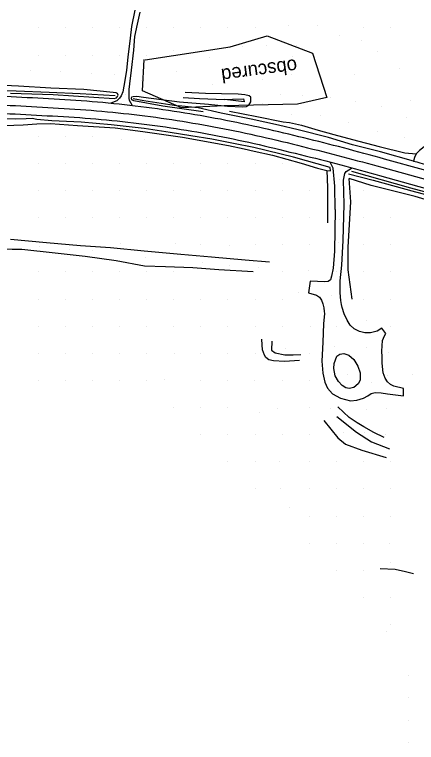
# Model space of a CAD drawing. Extents: x 524772 to 528246, y 273285 to 283088.
# Drawn here: x 526618.3 to 526762.8, y 276736 to 276997.8 of the extents above; entities that cross this region are included whole.
import ezdxf

# ---------------------------------------------------------------- set-up
doc = ezdxf.new("R2010")
doc.units = 0
for name, color, linetype in [('Exist DTM Crownline', 7, 'Continuous'), ('Exist Roads EOP', 7, 'Continuous'), ('Old_Level_12', 7, 'Continuous'), ('PH Exist DTM Breakline', 7, 'Continuous'), ('PH Exist DTM Point', 7, 'Continuous')]:
    doc.layers.add(name, color=color, linetype=linetype)

msp = doc.modelspace()

# ---------------------------------------------------------------- linework, layer by layer
at = {"layer": 'Exist DTM Crownline'}
msp.add_lwpolyline([(526750.37, 276942.86), (526764.67, 276938.9), (526778.8, 276934.96), (526793.27, 276930.79), (526807.53, 276926.68), (526821.79, 276922.52), (526835.38, 276918.67)], dxfattribs=at)
msp.add_spline([(526583.97, 276966.24), (526599.66, 276965.74), (526614.74, 276965.2), (526630.2, 276964.39), (526645.85, 276963.33), (526661.32, 276961.81), (526676.76, 276959.7), (526691.88, 276957.05), (526706.98, 276953.91), (526721.87, 276950.32), (526736.38, 276946.62), (526750.37, 276942.86)], degree=3, dxfattribs=at)
at = {"layer": 'Exist Roads EOP'}
for points in [[(526836.42, 276921.52), (526822.33, 276925.55), (526808.37, 276929.65), (526793.93, 276933.83), (526779.84, 276937.9), (526765.3, 276941.89), (526751.28, 276945.8)], [(526749.57, 276939.93), (526763.73, 276935.98), (526778.11, 276931.99), (526792.34, 276927.88), (526806.77, 276923.72), (526820.77, 276919.62), (526834.6, 276915.64)]]:
    msp.add_lwpolyline(points, dxfattribs=at)
for points in [[(526751.28, 276945.8), (526736.57, 276949.8), (526722.35, 276953.39), (526707.97, 276956.82), (526692.31, 276960.1), (526677.62, 276962.64), (526661.69, 276964.87), (526646.17, 276966.42), (526630.53, 276967.44), (526615.07, 276968.27), (526599.68, 276968.88), (526584.17, 276969.32)], [(526584.09, 276963.24), (526599.5, 276962.76), (526614.64, 276962.19), (526630, 276961.4), (526645.59, 276960.41), (526661, 276958.88), (526676.37, 276956.79), (526691.31, 276954.16), (526706.26, 276950.99), (526720.99, 276947.43), (526735.68, 276943.74), (526749.57, 276939.93)]]:
    msp.add_spline(points, degree=3, dxfattribs=at)
at = {"layer": 'Old_Level_12'}
msp.add_lwpolyline([(526665.21, 276981.52), (526695.79, 276986.19), (526709.17, 276990.14), (526725.41, 276983.88), (526730.54, 276967.96), (526720, 276965.59), (526693.64, 276964.91), (526678.35, 276964.28), (526664.24, 276970.4), (526664.9, 276981.56)], dxfattribs=at)
at = {"layer": 'PH Exist DTM Breakline'}
for points in [[(526661.56, 276999.35), (526660.35, 276993.52), (526659.86, 276989.24), (526659.01, 276982.43), (526658.48, 276977.78), (526658.01, 276974.78), (526657.52, 276972.02), (526657.16, 276969.94), (526656.57, 276968.53), (526656.01, 276967.71), (526655.12, 276966.75), (526652.91, 276965.93)], [(526660.54, 276965.17), (526659.67, 276966.87), (526659.44, 276967.65), (526659.44, 276969.3), (526659.53, 276970.8), (526659.74, 276972.91), (526660.29, 276977.75), (526661.12, 276984.94), (526661.58, 276989.89), (526662.44, 276994.32), (526663.45, 276998.59)], [(526654.5, 276968.49), (526641.9, 276969.23), (526630.71, 276969.76), (526618.83, 276970.2), (526609.89, 276970.38), (526602.6, 276970.41), (526593.89, 276971.19), (526584.11, 276971.71), (526572.09, 276971.82), (526560.52, 276972.33), (526547.76, 276972.58), (526530.62, 276973.42), (526512.6, 276973.83)], [(526616.81, 276969.48), (526632.17, 276969), (526654.09, 276967.53), (526655, 276967.81), (526655.34, 276968.28), (526655.49, 276968.82), (526655.33, 276969.42), (526654.87, 276969.57), (526653.77, 276969.69), (526643.23, 276970.83), (526631.33, 276971.24), (526619.69, 276971.96), (526597.29, 276973.07)], [(526686.14, 276962.73), (526671.55, 276964.86), (526661.17, 276966.7), (526660.5, 276967.15), (526660.31, 276967.65), (526660.44, 276968.16), (526660.89, 276968.35), (526662.31, 276968.4), (526664.63, 276968.12), (526677.65, 276966.36)], [(526660.96, 276967.54), (526664.75, 276966.83), (526677.2, 276964.98)], [(526677.65, 276966.36), (526687.98, 276965.57), (526694.86, 276964.87), (526700.24, 276964.6), (526701.68, 276964.72), (526702.55, 276965.16), (526703.31, 276966.39), (526703.31, 276967.25), (526703.22, 276968.1), (526702.71, 276968.57), (526701.12, 276968.9), (526698.66, 276969.17), (526692.67, 276969.31), (526686.92, 276969.35), (526679.65, 276969.7)], [(526678.93, 276967.99), (526684.81, 276967.62), (526690.79, 276967.36), (526693.86, 276967.2), (526696.62, 276967.3), (526700.67, 276967.43), (526700.87, 276966.34)], [(526761.81, 276945.04), (526749.87, 276948.43), (526739.86, 276950.94), (526731.24, 276953.51), (526720.31, 276956.26), (526713.18, 276957.94), (526703.37, 276960.12), (526692.59, 276962.34), (526684.34, 276964.22), (526677.2, 276964.98)], [(526700.87, 276966.34), (526693.86, 276967.2)], [(526664.84, 276956.78), (526653.07, 276958.11), (526642.2, 276959.1), (526631.63, 276959.55), (526626.34, 276960.01), (526624.64, 276960.45), (526622.48, 276960.28), (526618.48, 276960.19), (526613.85, 276960.33), (526611.8, 276960.25), (526610.64, 276960.48), (526603.66, 276960.54), (526594.14, 276960.83), (526583.23, 276960.97), (526572.55, 276961.32), (526562.82, 276961.68), (526552.87, 276962.01), (526537.98, 276962.47), (526526.73, 276962.92)], [(526695.59, 276963), (526705.38, 276961.06), (526714.84, 276959.25), (526717.22, 276958.91), (526721.45, 276957.95), (526727.49, 276956.21), (526733.13, 276954.58), (526739.87, 276952.85), (526749.41, 276950.34), (526758.7, 276948.03), (526762.68, 276947.65)], [(526611.98, 276958.53), (526615.48, 276957.88), (526618.07, 276957.94), (526621.38, 276958.12), (526626.33, 276958.44), (526631.2, 276958.54), (526640.87, 276957.93), (526654.52, 276957.08), (526664.47, 276955.7)], [(526664.47, 276955.7), (526678.69, 276953.63), (526695.2, 276950.64), (526700.85, 276949.44), (526704.48, 276948.7), (526711.01, 276947.22), (526721.32, 276944.38), (526727.24, 276942.56), (526730.64, 276941.67), (526731.96, 276941.56), (526731.81, 276942.76)], [(526731.81, 276942.76), (526718.59, 276946.49), (526704.39, 276949.97), (526697.03, 276951.41), (526689.28, 276952.94), (526681.64, 276954.13), (526674.29, 276955.3), (526664.84, 276956.78)], [(526768.56, 276951.85), (526765.55, 276950.18), (526763.88, 276948.91), (526762.68, 276947.65), (526762.1, 276946.33), (526761.81, 276945.04), (526762.96, 276944.79), (526764.02, 276944.46), (526771.64, 276942.23), (526778.71, 276939.92), (526782.68, 276938.86)], [(526733.58, 276927.68), (526733.45, 276936.06), (526732.89, 276942.52), (526731.79, 276944.63)], [(526730.64, 276941.67), (526730.84, 276935.56), (526730.85, 276922.82)], [(526736.87, 276929.55), (526736.55, 276938.2), (526737.02, 276940.57), (526737.52, 276941.34), (526739.48, 276942.54)], [(526739.7, 276895.42), (526738.23, 276905.99), (526738.22, 276914.14), (526739.19, 276930.37), (526738.61, 276938.81)], [(526738.35, 276940.53), (526747.31, 276938.2), (526762.51, 276934.02), (526776.41, 276930.39), (526784.62, 276927.99), (526793.3, 276925.2), (526805.33, 276921.83), (526806.15, 276921.58)], [(526803.03, 276920.34), (526796.68, 276922.37), (526794.11, 276923.24), (526791.08, 276924.16), (526788.29, 276925), (526785.6, 276925.82), (526783.07, 276926.61), (526774.71, 276928.99), (526768.41, 276930.59), (526762.35, 276932.29), (526746.52, 276936.26), (526738.61, 276938.81)], [(526807.34, 276922.06), (526795.64, 276925.42), (526783.59, 276929.26), (526760.81, 276935.38), (526739.56, 276941.34)], [(526735.92, 276893.49), (526735.62, 276894.98), (526735.4, 276897.73), (526735.43, 276901.97), (526736, 276907.68), (526736.45, 276916.51), (526736.87, 276929.55)], [(526733.58, 276927.68), (526733.33, 276912.66), (526732.9, 276906.54), (526732.31, 276903.7), (526731.87, 276902.43), (526731.09, 276901.83), (526729.87, 276901.7), (526724.54, 276901.95), (526723.97, 276897.67), (526726.85, 276896.89), (526727.97, 276896.08), (526728.62, 276895.03), (526729.21, 276893.74), (526729.56, 276892.26), (526729.68, 276891)], [(526616.87, 276916.96), (526629.79, 276915.78), (526642.05, 276914.66), (526652.73, 276914.03), (526664.91, 276912.85), (526678.1, 276911.64), (526689.1, 276910.63), (526701.24, 276909.56), (526709.97, 276908.82)], [(526704.07, 276905.28), (526691.8, 276905.93), (526682.37, 276906.72), (526672.55, 276907), (526664.99, 276907.28), (526654.84, 276909.2), (526643.68, 276910.74), (526632.89, 276911.95), (526620.9, 276913.25), (526617.42, 276913.3), (526612.98, 276913.4), (526608.06, 276913.65)], [(526729.68, 276891), (526729.74, 276890.29), (526729.42, 276886.55), (526729.13, 276879.95), (526728.85, 276873.17), (526729.2, 276868.81), (526729.87, 276865.51), (526730.87, 276863.44), (526732.67, 276861.41), (526735.48, 276859.81), (526739.05, 276858.91), (526741.41, 276859.04), (526743.72, 276859.77), (526745.29, 276860.68), (526746.52, 276861.47), (526747.97, 276861.87), (526750.18, 276861.69), (526752.41, 276861.38), (526758.12, 276860.62), (526758.19, 276863.26), (526754.73, 276864.16), (526753.46, 276864.72), (526752.35, 276865.72), (526751.53, 276867), (526750.87, 276868.88), (526750.53, 276872.37), (526750.54, 276874.69), (526750.41, 276876.69), (526750.49, 276878.65), (526750.66, 276880.55), (526751.29, 276882.26), (526751.8, 276883.02), (526750.32, 276884.95), (526748.64, 276883.92), (526746.29, 276883.33), (526744.21, 276883.29), (526742.28, 276883.74), (526740.45, 276884.78), (526739.04, 276886.02), (526737.86, 276887.89), (526736.83, 276890.13), (526736.12, 276892.46), (526735.92, 276893.49)], [(526720.75, 276873.4), (526715.37, 276872.97), (526711.39, 276873.29), (526709.78, 276873.65), (526708.66, 276874.43), (526708.13, 276875.33), (526707.51, 276877.23), (526707.35, 276879.02), (526707.23, 276881.07)], [(526710.77, 276880.32), (526710.65, 276877.02), (526712.01, 276876.13), (526715.51, 276875.44), (526718.5, 276875.39), (526721.19, 276875.56)], [(526733.61, 276867.88), (526733.12, 276870.52), (526733.18, 276872.29), (526734.16, 276874.96), (526735.24, 276875.61), (526736.72, 276875.82), (526738.49, 276875.28), (526740.32, 276873.77), (526741.79, 276871.35), (526742.54, 276868.87), (526742.55, 276866.24), (526741.83, 276865.01), (526740.24, 276863.7), (526738.64, 276863.33), (526737.47, 276863.58), (526736.12, 276864.42), (526734.79, 276865.82), (526733.61, 276867.88)], [(526751.25, 276845.67), (526747.54, 276847.49), (526743.94, 276849.45), (526741.44, 276850.93), (526738.66, 276852.85), (526734.54, 276856.67)], [(526734.19, 276853.25), (526741.24, 276847.57), (526746.67, 276844.13), (526753.14, 276841.57)], [(526729.47, 276851.81), (526734.5, 276845.56), (526737.33, 276843.32), (526743.2, 276841.06), (526751.93, 276838.44)], [(526749.73, 276798.56), (526755.14, 276798.3), (526758.83, 276797.51), (526761.79, 276796.7)]]:
    msp.add_lwpolyline(points, dxfattribs=at)
at = {"layer": 'PH Exist DTM Point'}
for p, q in [((526716.71, 276993.78), (526716.71, 276993.78)), ((526727.06, 276993.75), (526727.06, 276993.75)), ((526626.74, 276992.97), (526626.74, 276992.97)), ((526636.49, 276992.97), (526636.49, 276992.97)), ((526646.25, 276992.97), (526646.25, 276992.97)), ((526656, 276992.97), (526656, 276992.97)), ((526665.75, 276992.97), (526665.75, 276992.97)), ((526675.48, 276992.98), (526675.48, 276992.98)), ((526685.26, 276992.97), (526685.26, 276992.97)), ((526695.01, 276992.97), (526695.01, 276992.97)), ((526704.77, 276992.97), (526704.77, 276992.97)), ((526743.76, 276992.99), (526743.76, 276992.99)), ((526753.53, 276992.97), (526753.53, 276992.97)), ((526735.07, 276990.07), (526735.07, 276990.07)), ((526743.2, 276988.59), (526743.2, 276988.59)), ((526700.4, 276986.43), (526700.4, 276986.43)), ((526708.82, 276986.7), (526708.82, 276986.7)), ((526719.56, 276986.57), (526719.56, 276986.57)), ((526675.31, 276984.93), (526675.31, 276984.93)), ((526684.05, 276984.39), (526684.05, 276984.39)), ((526748.73, 276984.4), (526748.73, 276984.4)), ((526626.74, 276983.22), (526626.74, 276983.22)), ((526636.49, 276983.22), (526636.49, 276983.22)), ((526646.25, 276983.22), (526646.25, 276983.22)), ((526656, 276983.22), (526656, 276983.22)), ((526665.75, 276983.22), (526665.75, 276983.22)), ((526688.33, 276982.19), (526688.33, 276982.19)), ((526718.36, 276982.65), (526718.36, 276982.65)), ((526756.86, 276978.4), (526756.86, 276978.4)), ((526623.85, 276977.54), (526623.85, 276977.54)), ((526634.96, 276977.35), (526634.96, 276977.35)), ((526645.93, 276976.72), (526645.93, 276976.72)), ((526654.35, 276976.3), (526654.35, 276976.3)), ((526676.69, 276977.16), (526676.69, 276977.16)), ((526699.36, 276977.41), (526699.36, 276977.41)), ((526717.88, 276976.09), (526717.88, 276976.09)), ((526740.57, 276976.36), (526740.57, 276976.36)), ((526663.79, 276973.95), (526663.79, 276973.95)), ((526707.36, 276974.4), (526707.36, 276974.4)), ((526689.62, 276972.68), (526689.62, 276972.68)), ((526658.26, 276969.2), (526658.26, 276969.2)), ((526713.79, 276968.99), (526713.79, 276968.99)), ((526721.69, 276968.71), (526721.69, 276968.71)), ((526731.97, 276967.94), (526731.97, 276967.94)), ((526707.52, 276965.75), (526707.52, 276965.75)), ((526740.92, 276966.42), (526740.92, 276966.42)), ((526760.54, 276966.69), (526760.54, 276966.69)), ((526750.37, 276964.65), (526750.37, 276964.65)), ((526718.02, 276961.73), (526718.02, 276961.73)), ((526728.44, 276961.47), (526728.44, 276961.47)), ((526759.11, 276960.83), (526759.11, 276960.83)), ((526738.51, 276959.1), (526738.51, 276959.1)), ((526748.72, 276955.89), (526748.72, 276955.89)), ((526626.74, 276953.96), (526626.74, 276953.96)), ((526636.49, 276953.96), (526636.49, 276953.96)), ((526646.25, 276953.96), (526646.25, 276953.96)), ((526656.6, 276952.79), (526656.6, 276952.79)), ((526665.11, 276952.72), (526665.11, 276952.72)), ((526758.67, 276953.39), (526758.67, 276953.39)), ((526626.74, 276944.21), (526626.74, 276944.21)), ((526636.49, 276944.21), (526636.49, 276944.21)), ((526646.25, 276944.21), (526646.25, 276944.21)), ((526656, 276944.21), (526656, 276944.21)), ((526665.75, 276944.21), (526665.75, 276944.21)), ((526675.51, 276944.21), (526675.51, 276944.21)), ((526685.26, 276944.21), (526685.26, 276944.21)), ((526695.01, 276944.21), (526695.01, 276944.21)), ((526704.77, 276944.21), (526704.77, 276944.21)), ((526714.52, 276944.21), (526714.52, 276944.21)), ((526735.08, 276938.46), (526735.08, 276938.46)), ((526626.74, 276934.45), (526626.74, 276934.45)), ((526636.49, 276934.45), (526636.49, 276934.45)), ((526646.25, 276934.45), (526646.25, 276934.45)), ((526656, 276934.45), (526656, 276934.45)), ((526665.75, 276934.45), (526665.75, 276934.45)), ((526675.51, 276934.45), (526675.51, 276934.45)), ((526685.26, 276934.45), (526685.26, 276934.45)), ((526694.99, 276934.47), (526694.99, 276934.47)), ((526704.77, 276934.45), (526704.77, 276934.45)), ((526714.52, 276934.45), (526714.52, 276934.45)), ((526724.27, 276934.45), (526724.27, 276934.45)), ((526743.78, 276934.45), (526743.78, 276934.45)), ((526626.74, 276924.7), (526626.74, 276924.7)), ((526636.49, 276924.7), (526636.49, 276924.7)), ((526646.25, 276924.7), (526646.25, 276924.7)), ((526656, 276924.7), (526656, 276924.7)), ((526665.75, 276924.7), (526665.75, 276924.7)), ((526675.51, 276924.7), (526675.51, 276924.7)), ((526685.26, 276924.7), (526685.26, 276924.7)), ((526695.01, 276924.7), (526695.01, 276924.7)), ((526704.77, 276924.7), (526704.77, 276924.7)), ((526714.52, 276924.7), (526714.52, 276924.7)), ((526724.27, 276924.7), (526724.27, 276924.7)), ((526735.25, 276923.95), (526735.25, 276923.95)), ((526743.78, 276924.7), (526743.78, 276924.7)), ((526753.51, 276924.71), (526753.51, 276924.71)), ((526656.35, 276915.61), (526656.35, 276915.61)), ((526676, 276915.61), (526676, 276915.61)), ((526734.91, 276915.79), (526734.91, 276915.79)), ((526627.36, 276914.4), (526627.36, 276914.4)), ((526638, 276913.26), (526638, 276913.26)), ((526646.48, 276912.8), (526646.48, 276912.8)), ((526685.26, 276914.95), (526685.26, 276914.95)), ((526695.53, 276914.62), (526695.53, 276914.62)), ((526704.77, 276914.95), (526704.77, 276914.95)), ((526714.52, 276914.95), (526714.52, 276914.95)), ((526724.27, 276914.95), (526724.27, 276914.95)), ((526743.78, 276914.95), (526743.78, 276914.95)), ((526753.53, 276914.95), (526753.53, 276914.95)), ((526665.38, 276910.54), (526665.38, 276910.54)), ((526686, 276908.75), (526686, 276908.75)), ((526695.58, 276907.57), (526695.58, 276907.57)), ((526626.74, 276905.19), (526626.74, 276905.19)), ((526636.49, 276905.19), (526636.49, 276905.19)), ((526646.25, 276905.19), (526646.25, 276905.19)), ((526656, 276905.19), (526656, 276905.19)), ((526665.75, 276905.19), (526665.75, 276905.19)), ((526675.51, 276905.19), (526675.51, 276905.19)), ((526706.17, 276906.67), (526706.17, 276906.67)), ((526714.52, 276905.19), (526714.52, 276905.19)), ((526724.13, 276905.84), (526724.13, 276905.84)), ((526734.15, 276905.21), (526734.15, 276905.21)), ((526743.78, 276905.19), (526743.78, 276905.19)), ((526753.53, 276905.19), (526753.53, 276905.19)), ((526720.4, 276897.95), (526720.4, 276897.95)), ((526626.74, 276895.44), (526626.74, 276895.44)), ((526636.49, 276895.44), (526636.49, 276895.44)), ((526646.25, 276895.44), (526646.25, 276895.44)), ((526656, 276895.44), (526656, 276895.44)), ((526665.75, 276895.44), (526665.75, 276895.44)), ((526675.51, 276895.44), (526675.51, 276895.44)), ((526685.26, 276895.44), (526685.26, 276895.44)), ((526695.01, 276895.44), (526695.01, 276895.44)), ((526704.77, 276895.44), (526704.77, 276895.44)), ((526714.52, 276895.44), (526714.52, 276895.44)), ((526732.28, 276896.82), (526732.28, 276896.82)), ((526743.78, 276895.44), (526743.78, 276895.44)), ((526753.53, 276895.44), (526753.53, 276895.44)), ((526744.7, 276887.6), (526744.7, 276887.6)), ((526626.74, 276885.68), (526626.74, 276885.68)), ((526636.49, 276885.68), (526636.49, 276885.68)), ((526646.25, 276885.68), (526646.25, 276885.68)), ((526656, 276885.68), (526656, 276885.68)), ((526665.75, 276885.68), (526665.75, 276885.68)), ((526675.51, 276885.68), (526675.51, 276885.68)), ((526685.26, 276885.68), (526685.26, 276885.68)), ((526695.01, 276885.68), (526695.01, 276885.68)), ((526704.77, 276885.68), (526704.77, 276885.68)), ((526714.52, 276885.68), (526714.52, 276885.68)), ((526724.59, 276885.46), (526724.59, 276885.46)), ((526734.05, 276885.69), (526734.05, 276885.69)), ((526753.49, 276885.71), (526753.49, 276885.71)), ((526626.74, 276875.93), (526626.74, 276875.93)), ((526636.49, 276875.93), (526636.49, 276875.93)), ((526646.25, 276875.93), (526646.25, 276875.93)), ((526656, 276875.93), (526656, 276875.93)), ((526665.75, 276875.93), (526665.75, 276875.93)), ((526675.7, 276876.05), (526675.7, 276876.05)), ((526685.26, 276875.93), (526685.26, 276875.93)), ((526695.01, 276875.93), (526695.01, 276875.93)), ((526704.77, 276875.93), (526704.77, 276875.93)), ((526715.64, 276877.72), (526715.64, 276877.72)), ((526724.27, 276875.93), (526724.27, 276875.93)), ((526733.39, 276878.52), (526733.39, 276878.52)), ((526744.83, 276878.12), (526744.83, 276878.12)), ((526752.65, 276876.38), (526752.65, 276876.38)), ((526738.04, 276868.49), (526738.04, 276868.49)), ((526761.31, 276868.2), (526761.31, 276868.2)), ((526626.74, 276866.18), (526626.74, 276866.18)), ((526636.49, 276866.18), (526636.49, 276866.18)), ((526646.25, 276866.18), (526646.25, 276866.18)), ((526656, 276866.18), (526656, 276866.18)), ((526665.75, 276866.18), (526665.75, 276866.18)), ((526672.35, 276866.6), (526672.35, 276866.6)), ((526685.26, 276866.18), (526685.26, 276866.18)), ((526695.01, 276866.18), (526695.01, 276866.18)), ((526704.74, 276866.19), (526704.74, 276866.19)), ((526714.52, 276866.18), (526714.52, 276866.18)), ((526724.28, 276866.16), (526724.28, 276866.16)), ((526752.43, 276867.88), (526752.43, 276867.88)), ((526746.8, 276865.44), (526746.8, 276865.44)), ((526675.51, 276856.42), (526675.51, 276856.42)), ((526685.26, 276856.42), (526685.26, 276856.42)), ((526695.01, 276856.42), (526695.01, 276856.42)), ((526712.95, 276856.21), (526712.95, 276856.21)), ((526724.25, 276856.44), (526724.25, 276856.44)), ((526731.95, 276856.12), (526731.95, 276856.12)), ((526744.93, 276855.86), (526744.93, 276855.86)), ((526752.2, 276856.13), (526752.2, 276856.13)), ((526706.22, 276854.68), (526706.22, 276854.68)), ((526736.49, 276847.4), (526736.49, 276847.4)), ((526744.11, 276847.48), (526744.11, 276847.48)), ((526685.26, 276846.67), (526685.26, 276846.67)), ((526695.01, 276846.67), (526695.01, 276846.67)), ((526704.77, 276846.67), (526704.77, 276846.67)), ((526714.52, 276846.67), (526714.52, 276846.67)), ((526724.3, 276846.66), (526724.3, 276846.66)), ((526751.78, 276846.8), (526751.78, 276846.8)), ((526695.01, 276836.92), (526695.01, 276836.92)), ((526704.77, 276836.92), (526704.77, 276836.92)), ((526713.47, 276837.02), (526713.47, 276837.02)), ((526724.27, 276836.92), (526724.27, 276836.92)), ((526734.03, 276836.92), (526734.03, 276836.92)), ((526743.76, 276836.91), (526743.76, 276836.91)), ((526753.53, 276836.92), (526753.53, 276836.92)), ((526704.77, 276827.16), (526704.77, 276827.16)), ((526713.86, 276827.28), (526713.86, 276827.28)), ((526724.27, 276827.16), (526724.27, 276827.16)), ((526734.03, 276827.16), (526734.03, 276827.16)), ((526743.78, 276827.16), (526743.78, 276827.16)), ((526753.53, 276827.16), (526753.53, 276827.16)), ((526717.01, 276820.65), (526717.01, 276820.65)), ((526724.27, 276817.41), (526724.27, 276817.41)), ((526734.03, 276817.41), (526734.03, 276817.41)), ((526743.76, 276817.42), (526743.76, 276817.42)), ((526753.53, 276817.41), (526753.53, 276817.41)), ((526724.27, 276807.66), (526724.27, 276807.66)), ((526734.03, 276807.66), (526734.03, 276807.66)), ((526743.81, 276807.64), (526743.81, 276807.64)), ((526753.06, 276807.7), (526753.06, 276807.7)), ((526753.61, 276800.76), (526753.61, 276800.76)), ((526734.03, 276797.9), (526734.03, 276797.9)), ((526743.78, 276797.9), (526743.78, 276797.9)), ((526743.78, 276788.15), (526743.78, 276788.15)), ((526753.53, 276788.15), (526753.53, 276788.15)), ((526753.53, 276778.39), (526753.53, 276778.39)), ((526752, 276776), (526752, 276776)), ((526760, 276760), (526760, 276760)), ((526760, 276752), (526760, 276752)), ((526760, 276744), (526760, 276744)), ((526760, 276736), (526760, 276736))]:
    msp.add_line(p, q, dxfattribs=at)

# ---------------------------------------------------------------- texts
at = {"layer": 'Old_Level_12'}
msp.add_text('obscured', height=5, rotation=187.5702, dxfattribs=at).set_placement((526719.59, 276981.79))

doc.saveas('drawing.dxf')
